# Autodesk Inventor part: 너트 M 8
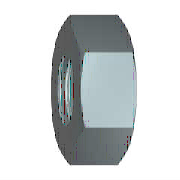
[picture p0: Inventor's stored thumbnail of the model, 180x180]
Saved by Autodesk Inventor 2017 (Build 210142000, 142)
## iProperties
IsCustomPart: 1
Created: 2012-02
Part Number: 너트 M 8
Material: 강철, 연강
Description: 6각 너트 및 6각 가는 너트
Document SubType Name: Modeling
Standard: KS B 1012
Designer: mduedu
Standards Organization: KS
Language: ko-KR
Size Designation: M 8
Categories: <MemberInstance><Categories><Category DisplayName="조임쇠" InternalName="e4da775c-781d-43d5-af7c-5136215cf5a6" Mnemonic="FSTN"><Category DisplayName="너트" InternalN
Density: 1 g/cm^3
Appearance: 강철
Author: mduedu
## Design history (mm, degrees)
sketch "스케치1"
  geometry: L1 (-7.506, 0)-(-3.753, 6.5); L2 (-3.753, 6.5)-(3.753, 6.5); L3 (3.753, 6.5)-(7.506, 0); L4 (7.506, 0)-(3.753, -6.5); L5 (3.753, -6.5)-(-3.753, -6.5); L6 (-3.753, -6.5)-(-7.506, 0); 2 further points
  constraints: 12 end point, 1 coincident, 1 horizontal, 11 other
  dimensions: "d0" = 15.01111 distance of L3.end L1.start (= 1.1547 x SW)
extrude "본체" new body sketch "스케치1" distance "d1" = 5 (= KOH); taper "d2" = 0 deg
sketch "스케치2"
  geometry: L1 (0, 3.753)-(0, 7.506) reference; L2 (0, 7.506)-(5, 7.506) reference; L3 (5, 3.753)-(5, 7.506) reference; L4 (-1, 0)-(6, 0) reference; L5 (0.581, 7.506)-(0, 6.5); L6 (4.419, 7.506)-(5, 6.5)
  constraints: 4 end point, 4 point on line
  dimensions: "d3" = 30 deg angle of L1 L5 (= ANG1); "d4" = 30 deg angle of L3 L6 (= ANG2); "d5" = 13 diameter of L5.end L4 (= SW0); "d6" = 13 diameter of L6.end L4 (= SW01)
revolve "모따기1" sketch "스케치2" stored, may be unused: angle "d7" = 90 deg
sketch "스케치3"
  geometry: A1 r 6.5 centre (0, 0) between (-3.25, -5.629) and (3.25, -5.629) reference; 1 further point
  constraints: 1 coincident
hole "스레드" sketch "스케치3" at (0, 0) diameter "d25" = 6.647; stored, may be unused: countersink angle "d29" = 82 deg, drill point angle "d31" = 118 deg; dims "d26" = 6, "d27" = 4, "d28" = 2, "d30" = 8
workaxis "Work Axis1"
workplane "Work Plane1"
body "Solid1"
chamfer "모따기2" distance "d8" = 0.67658 (= -0.5 x GD1 + 0.5 x NND); stored, may be unused: angle "d9" = 30 deg, second distance "d40" = 0.67658 (= -0.5 x GD1 + 0.5 x NND)
chamfer "모따기3" distance "d10" = 0.67658 (= -0.5 x GD1 + 0.5 x NND); stored, may be unused: angle "d11" = 30 deg, second distance "d41" = 0.67658 (= -0.5 x GD1 + 0.5 x NND)
other parameters: "ANG1" = 30 deg [user parameter; used in 1 equation term], "ANG2" = 30 deg [user parameter; used in 1 equation term], "NND" = 8 [user parameter; used in 4 equation terms], "KOH" = 5 [user parameter; used in 1 equation term], "SW" = 13 [user parameter; used in 4 equation terms], "SW0" = 13 (= SW) [user parameter; used in 1 equation term], "SW01" = 13 (= SW) [user parameter; used in 1 equation term], "GD1" = 6.64684 (computed from THREADDIA, PTC, TOA) [user parameter; used in 4 equation terms], "d13" = 0, "d14" = 0, "d39" = 0, "d42" = 0, "GUL" = 0.67658 (= 0.541266 x PTC) [user parameter], "TPU" = 8 (computed from PTC) [user parameter], "THREADDIA" = 8 [user parameter; used in 1 equation term], "TOA" = 30 deg [user parameter; used in 1 equation term], "PTC" = 1.25 [user parameter; used in 4 equation terms], "E0" = 15.015 (= 1.155 x SW) [user parameter], "GAL" = 0.67658 (= 0.541266 x PTC) [user parameter]
